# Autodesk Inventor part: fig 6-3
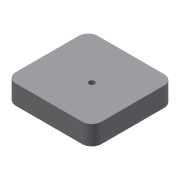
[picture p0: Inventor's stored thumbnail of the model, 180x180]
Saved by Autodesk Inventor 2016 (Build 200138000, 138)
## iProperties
Created: 2004-05
Part Number: fig 6-3
Document SubType Name: Modeling
Designer: CADCIM Technologies
Manufacturer: Standard
Standards Organization: Custom
Density: 1 g/cm^3
Material: Generic
Appearance: Default
Author: CADCIM Technologies
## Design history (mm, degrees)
sketch "Sketch1"
  geometry: L1 (0, 0)-(44.293, 0); L2 (44.293, 0)-(44.293, 42.442); L3 (44.293, 42.442)-(0, 42.442); L4 (0, 42.442)-(0, 0)
  constraints: 8 end point, 2 parallel, 1 horizontal, 1 perpendicular
extrude "Extrusion1" new body sketch "Sketch1" distance "d0" = 10; taper "d1" = 0 deg
fillet "Fillet1" dims "d2" = 5
hole "Hole1" diameter "d6" = 3; stored, may be unused: countersink angle "d10" = 90 deg, drill point angle "d12" = 118 deg; dims "d4" = 20, "d5" = 20, "d7" = 6, "d8" = 4, "d9" = 2, "d11" = 8
body "Solid1"
